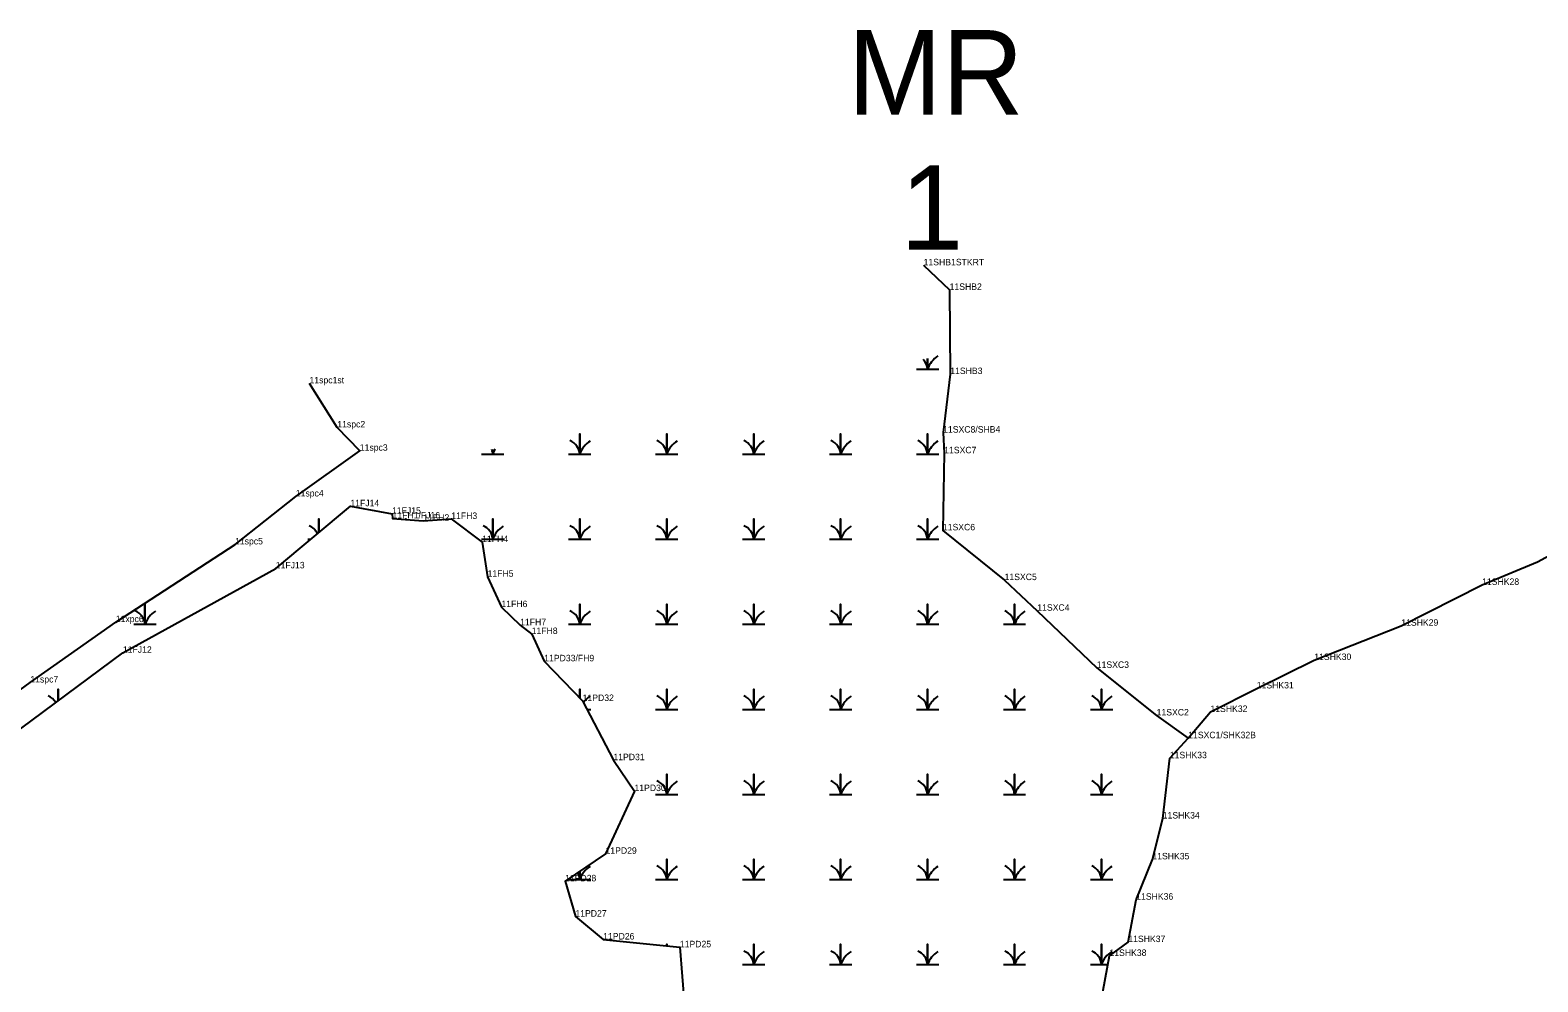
# Model space of a CAD drawing. Extents: x 2072529 to 2268796, y 436423 to 470406.
# Drawn here: x 2231902 to 2233068, y 447664 to 448400 of the extents above; entities that cross this region are included whole.
import ezdxf

# ---------------------------------------------------------------- set-up
doc = ezdxf.new("R2010")
doc.units = 0
for name, color, linetype in [('Default', 7, 'Continuous'), ('Exist Environmental Wetland Boundary', 7, 'Continuous'), ('Exist Environmental Wetland Boundary Cogo Comment', 7, 'Continuous'), ('Exist Hydro Jurisdictional Stream or Body of Water NEU Mitigable', 7, 'Continuous'), ('Exist Hydro Jurisdictional Stream or Body of Water NEU Mitigable Cogo Comment', 7, 'Continuous'), ('Exist Hydro Swamp or Marsh', 7, 'Continuous'), ('Old_Level_20', 7, 'Continuous')]:
    doc.layers.add(name, color=color, linetype=linetype)

msp = doc.modelspace()

# ---------------------------------------------------------------- linework, layer by layer
at = {"layer": 'Exist Environmental Wetland Boundary'}
msp.add_lwpolyline([(2231807.6, 447794.9), (2231974.2, 447918.4), (2232092.4, 447983.7), (2232150.1, 448031.7), (2232182.3, 448025.9), (2232182.7, 448022.3), (2232206.5, 448020.5), (2232228.1, 448021.9), (2232252, 448004), (2232256.2, 447977.2), (2232266.9, 447953.7), (2232281.4, 447939.7), (2232290.3, 447932.9), (2232300, 447911.8), (2232329.7, 447881.1), (2232353.5, 447835.3), (2232369.8, 447811.4), (2232347.4, 447762.9), (2232316.1, 447741.6), (2232324.1, 447714.3), (2232345.6, 447696.6), (2232404.9, 447690.6), (2232408.4, 447645.4)], dxfattribs=at)
at = {"layer": 'Exist Hydro Jurisdictional Stream or Body of Water NEU Mitigable'}
for points in [[(2232593.4, 448218.1), (2232613.5, 448199.1), (2232614, 448134), (2232608.5, 448088.7)], [(2230769.4, 447951.9), (2230820.5, 447870.1), (2230875.8, 447771.9), (2230917.6, 447710.6), (2230955.8, 447692.5), (2231037.5, 447706.9), (2231173.4, 447735.5), (2231315.3, 447761.1), (2231455.2, 447786.8), (2231613.2, 447790.3), (2231730.8, 447794.1), (2231802.3, 447822), (2231902.6, 447895.4), (2231968.7, 447942.1), (2232060.9, 448002.2), (2232107.9, 448039.3), (2232157.4, 448074.7), (2232140, 448092.7), (2232118.5, 448126.8)], [(2232608.5, 448088.7), (2232609.3, 448072.7), (2232608.3, 448013.1), (2232656, 447974.6), (2232681.3, 447950.9), (2232727.3, 447906.7), (2232773.6, 447869.9), (2232798, 447852.3)], [(2232612.7, 447313.1), (2232637.1, 447372.3), (2232659.7, 447420.7), (2232659.3, 447443.5), (2232665.8, 447482.5), (2232689.5, 447512.3), (2232693.2, 447533.5), (2232707, 447570), (2232725.1, 447618.2), (2232737.1, 447683.9), (2232751.7, 447694.6), (2232757.8, 447727.4), (2232770.3, 447758.6), (2232778.3, 447790.2), (2232783.8, 447836.8), (2232798, 447852.3), (2232815.2, 447872.6), (2232851, 447890.8), (2232895.5, 447912.8), (2232962.8, 447939.3), (2233025.3, 447970.9), (2233068.1, 447988.8), (2233109.1, 448010.9)]]:
    msp.add_lwpolyline(points, dxfattribs=at)
at = {"layer": 'Exist Hydro Swamp or Marsh'}
for points in [[(2232587.9, 448137.8), (2232596.5, 448137.8), (2232596.5, 448146.1)], [(2232596.5, 448146.1), (2232596.5, 448137.8), (2232605.1, 448137.8)], [(2232318.9, 448072), (2232327.5, 448072), (2232327.5, 448087.7), (2232327.5, 448072), (2232336.1, 448072)], [(2232386.1, 448072), (2232394.7, 448072), (2232394.7, 448087.7), (2232394.7, 448072), (2232403.3, 448072)], [(2232453.4, 448072), (2232462, 448072), (2232462, 448087.7), (2232462, 448072), (2232470.6, 448072)], [(2232520.6, 448072), (2232529.2, 448072), (2232529.2, 448087.7), (2232529.2, 448072), (2232537.8, 448072)], [(2232587.9, 448072), (2232596.5, 448072), (2232596.5, 448087.7), (2232596.5, 448072), (2232605.1, 448072)], [(2232251.6, 448072), (2232260.2, 448072), (2232260.2, 448075.7)], [(2232260.2, 448075.7), (2232260.2, 448072), (2232268.8, 448072)], [(2232125.7, 448011.4), (2232125.7, 448021.9), (2232125.7, 448011.4)], [(2232193, 448021.5), (2232193, 448021.9), (2232193, 448021.5)], [(2232251.6, 448006.2), (2232260.2, 448006.2), (2232260.2, 448021.9), (2232260.2, 448006.2), (2232268.8, 448006.2)], [(2232318.9, 448006.2), (2232327.5, 448006.2), (2232327.5, 448021.9), (2232327.5, 448006.2), (2232336.1, 448006.2)], [(2232386.1, 448006.2), (2232394.7, 448006.2), (2232394.7, 448021.9), (2232394.7, 448006.2), (2232403.3, 448006.2)], [(2232453.4, 448006.2), (2232462, 448006.2), (2232462, 448021.9), (2232462, 448006.2), (2232470.6, 448006.2)], [(2232520.6, 448006.2), (2232529.2, 448006.2), (2232529.2, 448021.9), (2232529.2, 448006.2), (2232537.8, 448006.2)], [(2232587.9, 448006.2), (2232596.5, 448006.2), (2232596.5, 448021.9), (2232596.5, 448006.2), (2232605.1, 448006.2)], [(2232066, 448006.2), (2232067.1, 448006.2)], [(2232117.1, 448006.2), (2232119.4, 448006.2)], [(2231982.6, 447940.4), (2231991.2, 447940.4), (2231991.2, 447956.1), (2231991.2, 447940.4), (2231999.8, 447940.4)], [(2232318.9, 447940.4), (2232327.5, 447940.4), (2232327.5, 447956.1), (2232327.5, 447940.4), (2232336.1, 447940.4)], [(2232386.1, 447940.4), (2232394.7, 447940.4), (2232394.7, 447956.1), (2232394.7, 447940.4), (2232403.3, 447940.4)], [(2232453.4, 447940.4), (2232462, 447940.4), (2232462, 447956.1), (2232462, 447940.4), (2232470.6, 447940.4)], [(2232520.6, 447940.4), (2232529.2, 447940.4), (2232529.2, 447956.1), (2232529.2, 447940.4), (2232537.8, 447940.4)], [(2232587.9, 447940.4), (2232596.5, 447940.4), (2232596.5, 447956.1), (2232596.5, 447940.4), (2232605.1, 447940.4)], [(2232655.1, 447940.4), (2232663.7, 447940.4), (2232663.7, 447956.1), (2232663.7, 447940.4), (2232672.3, 447940.4)], [(2231924, 447881.2), (2231924, 447890.3), (2231924, 447881.2)], [(2232327.5, 447883.4), (2232327.5, 447890.3), (2232327.5, 447883.4)], [(2232386.1, 447874.6), (2232394.7, 447874.6), (2232394.7, 447890.3), (2232394.7, 447874.6), (2232403.3, 447874.6)], [(2232453.4, 447874.6), (2232462, 447874.6), (2232462, 447890.3), (2232462, 447874.6), (2232470.6, 447874.6)], [(2232520.6, 447874.6), (2232529.2, 447874.6), (2232529.2, 447890.3), (2232529.2, 447874.6), (2232537.8, 447874.6)], [(2232587.9, 447874.6), (2232596.5, 447874.6), (2232596.5, 447890.3), (2232596.5, 447874.6), (2232605.1, 447874.6)], [(2232655.1, 447874.6), (2232663.7, 447874.6), (2232663.7, 447890.3), (2232663.7, 447874.6), (2232672.3, 447874.6)], [(2232722.4, 447874.6), (2232731, 447874.6), (2232731, 447890.3), (2232731, 447874.6), (2232739.6, 447874.6)], [(2232333.1, 447874.6), (2232336.1, 447874.6)], [(2232386.1, 447808.8), (2232394.7, 447808.8), (2232394.7, 447824.5), (2232394.7, 447808.8), (2232403.3, 447808.8)], [(2232453.4, 447808.8), (2232462, 447808.8), (2232462, 447824.5), (2232462, 447808.8), (2232470.6, 447808.8)], [(2232520.6, 447808.8), (2232529.2, 447808.8), (2232529.2, 447824.5), (2232529.2, 447808.8), (2232537.8, 447808.8)], [(2232587.9, 447808.8), (2232596.5, 447808.8), (2232596.5, 447824.5), (2232596.5, 447808.8), (2232605.1, 447808.8)], [(2232655.1, 447808.8), (2232663.7, 447808.8), (2232663.7, 447824.5), (2232663.7, 447808.8), (2232672.3, 447808.8)], [(2232722.4, 447808.8), (2232731, 447808.8), (2232731, 447824.5), (2232731, 447808.8), (2232739.6, 447808.8)], [(2232386.1, 447743), (2232394.7, 447743), (2232394.7, 447758.7), (2232394.7, 447743), (2232403.3, 447743)], [(2232453.4, 447743), (2232462, 447743), (2232462, 447758.7), (2232462, 447743), (2232470.6, 447743)], [(2232520.6, 447743), (2232529.2, 447743), (2232529.2, 447758.7), (2232529.2, 447743), (2232537.8, 447743)], [(2232587.9, 447743), (2232596.5, 447743), (2232596.5, 447758.7), (2232596.5, 447743), (2232605.1, 447743)], [(2232655.1, 447743), (2232663.7, 447743), (2232663.7, 447758.7), (2232663.7, 447743), (2232672.3, 447743)], [(2232722.4, 447743), (2232731, 447743), (2232731, 447758.7), (2232731, 447743), (2232739.6, 447743)], [(2232318.9, 447743), (2232327.5, 447743), (2232327.5, 447749.4)], [(2232327.5, 447749.4), (2232327.5, 447743), (2232336.1, 447743)], [(2232394.7, 447691.7), (2232394.7, 447692.9), (2232394.7, 447691.7)], [(2232453.4, 447677.2), (2232462, 447677.2), (2232462, 447692.9), (2232462, 447677.2), (2232470.6, 447677.2)], [(2232520.6, 447677.2), (2232529.2, 447677.2), (2232529.2, 447692.9), (2232529.2, 447677.2), (2232537.8, 447677.2)], [(2232587.9, 447677.2), (2232596.5, 447677.2), (2232596.5, 447692.9), (2232596.5, 447677.2), (2232605.1, 447677.2)], [(2232655.1, 447677.2), (2232663.7, 447677.2), (2232663.7, 447692.9), (2232663.7, 447677.2), (2232672.3, 447677.2)], [(2232722.4, 447677.2), (2232731, 447677.2), (2232731, 447692.9), (2232731, 447677.2), (2232735.8, 447677.2)]]:
    msp.add_lwpolyline(points, dxfattribs=at)
for centre, radius, start, end in [((2232614.7, 448131.7), 19.2, 122.1274, 161.6222), ((2232584.2, 448136.9), 12.3, 4.1403, 43.3796), ((2232315.2, 448071.1), 12.3, 4.1403, 67.535), ((2232345.7, 448065.9), 19.2, 122.1274, 161.6222), ((2232382.5, 448071.1), 12.3, 4.1403, 67.535), ((2232413, 448065.9), 19.2, 122.1274, 161.6222), ((2232449.7, 448071.1), 12.3, 4.1403, 67.535), ((2232480.2, 448065.9), 19.2, 122.1274, 161.6222), ((2232517, 448071.1), 12.3, 4.1403, 67.535), ((2232547.5, 448065.9), 19.2, 122.1274, 161.6222), ((2232584.2, 448071.1), 12.3, 4.1403, 67.535), ((2232614.7, 448065.9), 19.2, 122.1274, 161.6222), ((2232248, 448071.1), 12.3, 4.1403, 21.2935), ((2232278.5, 448065.9), 19.2, 148.249, 161.6222), ((2232113.5, 448005.3), 12.3, 25.1043, 67.535), ((2232248, 448005.3), 12.3, 4.1403, 67.535), ((2232278.5, 448000.1), 19.2, 122.1274, 161.6222), ((2232315.2, 448005.3), 12.3, 4.1403, 67.535), ((2232345.7, 448000.1), 19.2, 122.1274, 161.6222), ((2232382.5, 448005.3), 12.3, 4.1403, 67.535), ((2232413, 448000.1), 19.2, 122.1274, 161.6222), ((2232449.7, 448005.3), 12.3, 4.1403, 67.535), ((2232480.2, 448000.1), 19.2, 122.1274, 161.6222), ((2232517, 448005.3), 12.3, 4.1403, 67.535), ((2232547.5, 448000.1), 19.2, 122.1274, 161.6222), ((2232584.2, 448005.3), 12.3, 4.1403, 67.535), ((2232614.7, 448000.1), 19.2, 122.1274, 161.6222), ((2231979, 447939.5), 12.3, 4.1403, 67.535), ((2232009.5, 447934.3), 19.2, 122.1274, 161.6222), ((2232315.2, 447939.5), 12.3, 4.1403, 67.535), ((2232345.7, 447934.3), 19.2, 122.1274, 161.6222), ((2232382.5, 447939.5), 12.3, 4.1403, 67.535), ((2232413, 447934.3), 19.2, 122.1274, 161.6222), ((2232449.7, 447939.5), 12.3, 4.1403, 67.535), ((2232480.2, 447934.3), 19.2, 122.1274, 161.6222), ((2232517, 447939.5), 12.3, 4.1403, 67.535), ((2232547.5, 447934.3), 19.2, 122.1274, 161.6222), ((2232584.2, 447939.5), 12.3, 4.1403, 67.535), ((2232614.7, 447934.3), 19.2, 122.1274, 161.6222), ((2232651.5, 447939.5), 12.3, 4.1403, 67.535), ((2232682, 447934.3), 19.2, 122.1274, 161.6222), ((2231911.7, 447873.7), 12.3, 30.5555, 67.535), ((2232345.7, 447868.5), 19.2, 122.1274, 143.4024), ((2232382.5, 447873.7), 12.3, 4.1403, 67.535), ((2232413, 447868.5), 19.2, 122.1274, 161.6222), ((2232449.7, 447873.7), 12.3, 4.1403, 67.535), ((2232480.2, 447868.5), 19.2, 122.1274, 161.6222), ((2232517, 447873.7), 12.3, 4.1403, 67.535), ((2232547.5, 447868.5), 19.2, 122.1274, 161.6222), ((2232584.2, 447873.7), 12.3, 4.1403, 67.535), ((2232614.7, 447868.5), 19.2, 122.1274, 161.6222), ((2232651.5, 447873.7), 12.3, 4.1403, 67.535), ((2232682, 447868.5), 19.2, 122.1274, 161.6222), ((2232718.7, 447873.7), 12.3, 4.1403, 67.535), ((2232749.2, 447868.5), 19.2, 122.1274, 161.6222), ((2232382.5, 447807.9), 12.3, 4.1403, 67.535), ((2232413, 447802.7), 19.2, 122.1274, 161.6222), ((2232449.7, 447807.9), 12.3, 4.1403, 67.535), ((2232480.2, 447802.7), 19.2, 122.1274, 161.6222), ((2232517, 447807.9), 12.3, 4.1403, 67.535), ((2232547.5, 447802.7), 19.2, 122.1274, 161.6222), ((2232584.2, 447807.9), 12.3, 4.1403, 67.535), ((2232614.7, 447802.7), 19.2, 122.1274, 161.6222), ((2232651.5, 447807.9), 12.3, 4.1403, 67.535), ((2232682, 447802.7), 19.2, 122.1274, 161.6222), ((2232718.7, 447807.9), 12.3, 4.1403, 67.535), ((2232749.2, 447802.7), 19.2, 122.1274, 161.6222), ((2232345.7, 447736.9), 19.2, 122.1274, 161.6222), ((2232382.5, 447742.1), 12.3, 4.1403, 67.535), ((2232413, 447736.9), 19.2, 122.1274, 161.6222), ((2232449.7, 447742.1), 12.3, 4.1403, 67.535), ((2232480.2, 447736.9), 19.2, 122.1274, 161.6222), ((2232517, 447742.1), 12.3, 4.1403, 67.535), ((2232547.5, 447736.9), 19.2, 122.1274, 161.6222), ((2232584.2, 447742.1), 12.3, 4.1403, 67.535), ((2232614.7, 447736.9), 19.2, 122.1274, 161.6222), ((2232651.5, 447742.1), 12.3, 4.1403, 67.535), ((2232682, 447736.9), 19.2, 122.1274, 161.6222), ((2232718.7, 447742.1), 12.3, 4.1403, 67.535), ((2232749.2, 447736.9), 19.2, 122.1274, 161.6222), ((2232315.2, 447742.1), 12.3, 4.1403, 30.1347), ((2232449.7, 447676.3), 12.3, 4.1403, 67.535), ((2232480.2, 447671.1), 19.2, 122.1274, 161.6222), ((2232517, 447676.3), 12.3, 4.1403, 67.535), ((2232547.5, 447671.1), 19.2, 122.1274, 161.6222), ((2232584.2, 447676.3), 12.3, 4.1403, 67.535), ((2232614.7, 447671.1), 19.2, 122.1274, 161.6222), ((2232651.5, 447676.3), 12.3, 4.1403, 67.535), ((2232682, 447671.1), 19.2, 122.1274, 161.6222), ((2232718.7, 447676.3), 12.3, 4.1403, 67.535), ((2232749.2, 447671.1), 19.2, 122.1274, 161.6222)]:
    msp.add_arc(centre, radius, start, end, dxfattribs=at)
at = {"layer": 'Old_Level_20'}
for p, q in [((2232593.4, 448218.1), (2232593.4, 448218.1)), ((2232613.5, 448199.1), (2232613.5, 448199.1)), ((2232118.5, 448126.8), (2232118.5, 448126.8)), ((2232614, 448134), (2232614, 448134)), ((2232140, 448092.7), (2232140, 448092.7)), ((2232608.5, 448088.7), (2232608.5, 448088.7)), ((2232157.4, 448074.7), (2232157.4, 448074.7)), ((2232609.3, 448072.7), (2232609.3, 448072.7)), ((2232107.9, 448039.3), (2232107.9, 448039.3)), ((2232150.1, 448031.7), (2232150.1, 448031.7)), ((2232182.3, 448025.9), (2232182.3, 448025.9)), ((2232182.7, 448022.3), (2232182.7, 448022.3)), ((2232206.5, 448020.5), (2232206.5, 448020.5)), ((2232228.1, 448021.9), (2232228.1, 448021.9)), ((2232608.3, 448013.1), (2232608.3, 448013.1)), ((2232060.9, 448002.2), (2232060.9, 448002.2)), ((2232252, 448004), (2232252, 448004)), ((2232092.4, 447983.7), (2232092.4, 447983.7)), ((2233068.1, 447988.8), (2233068.1, 447988.8)), ((2232256.2, 447977.2), (2232256.2, 447977.2)), ((2232656, 447974.6), (2232656, 447974.6)), ((2233025.3, 447970.9), (2233025.3, 447970.9)), ((2232266.9, 447953.7), (2232266.9, 447953.7)), ((2232681.3, 447950.9), (2232681.3, 447950.9)), ((2231968.7, 447942.1), (2231968.7, 447942.1)), ((2232281.4, 447939.7), (2232281.4, 447939.7)), ((2232962.8, 447939.3), (2232962.8, 447939.3)), ((2232290.3, 447932.9), (2232290.3, 447932.9)), ((2231974.2, 447918.4), (2231974.2, 447918.4)), ((2232300, 447911.8), (2232300, 447911.8)), ((2232727.3, 447906.7), (2232727.3, 447906.7)), ((2232895.5, 447912.8), (2232895.5, 447912.8)), ((2231902.6, 447895.4), (2231902.6, 447895.4)), ((2232851, 447890.8), (2232851, 447890.8)), ((2232329.7, 447881.1), (2232329.7, 447881.1)), ((2232773.6, 447869.9), (2232773.6, 447869.9)), ((2232815.2, 447872.6), (2232815.2, 447872.6)), ((2232798, 447852.3), (2232798, 447852.3)), ((2232353.5, 447835.3), (2232353.5, 447835.3)), ((2232783.8, 447836.8), (2232783.8, 447836.8)), ((2232369.8, 447811.4), (2232369.8, 447811.4)), ((2232778.3, 447790.2), (2232778.3, 447790.2)), ((2232347.4, 447762.9), (2232347.4, 447762.9)), ((2232770.3, 447758.6), (2232770.3, 447758.6)), ((2232316.1, 447741.6), (2232316.1, 447741.6)), ((2232757.8, 447727.4), (2232757.8, 447727.4)), ((2232324.1, 447714.3), (2232324.1, 447714.3)), ((2232345.6, 447696.6), (2232345.6, 447696.6)), ((2232751.7, 447694.6), (2232751.7, 447694.6)), ((2232404.9, 447690.6), (2232404.9, 447690.6)), ((2232737.1, 447683.9), (2232737.1, 447683.9))]:
    msp.add_line(p, q, dxfattribs=at)

# ---------------------------------------------------------------- texts
at = {"layer": 'Default'}
for s, height, p in [('MR', 65.34, (2232534.8, 448334.7)), ('1', 65.3, (2232575.5, 448230.1))]:
    msp.add_text(s, height=height, dxfattribs=at).set_placement(p)
at = {"layer": 'Exist Environmental Wetland Boundary Cogo Comment'}
for s, p in [('11FJ14', (2232150.1, 448031.7)), ('11FJ15', (2232182.3, 448025.9)), ('11FH1/FJ16', (2232182.7, 448022.3)), ('11FH2', (2232206.5, 448020.5)), ('11FH3', (2232228.1, 448021.9)), ('11FH4', (2232252, 448004)), ('11FJ13', (2232092.4, 447983.7)), ('11FH5', (2232256.2, 447977.2)), ('11FH6', (2232266.9, 447953.7)), ('11FH7', (2232281.4, 447939.7)), ('11FH8', (2232290.3, 447932.9)), ('11FJ12', (2231974.2, 447918.4)), ('11PD33/FH9', (2232300, 447911.8)), ('11PD32', (2232329.7, 447881.1)), ('11PD31', (2232353.5, 447835.3)), ('11PD30', (2232369.8, 447811.4)), ('11PD29', (2232347.4, 447762.9)), ('11PD28', (2232316.1, 447741.6)), ('11PD27', (2232324.1, 447714.3)), ('11PD26', (2232345.6, 447696.6)), ('11PD25', (2232404.9, 447690.6))]:
    msp.add_text(s, height=5, dxfattribs=at).set_placement(p)
at = {"layer": 'Exist Hydro Jurisdictional Stream or Body of Water NEU Mitigable Cogo Comment'}
for s, p in [('11SHB1STKRT', (2232593.4, 448218.1)), ('11SHB2', (2232613.5, 448199.1)), ('11SHB3', (2232614, 448134)), ('11spc1st', (2232118.5, 448126.8)), ('11spc2', (2232140, 448092.7)), ('11SXC8/SHB4', (2232608.5, 448088.7)), ('11spc3', (2232157.4, 448074.7)), ('11SXC7', (2232609.3, 448072.7)), ('11spc4', (2232107.9, 448039.3)), ('11SXC6', (2232608.3, 448013.1)), ('11spc5', (2232060.9, 448002.2)), ('11SXC5', (2232656, 447974.6)), ('11SHK28', (2233025.3, 447970.9)), ('11SXC4', (2232681.3, 447950.9)), ('11xpc6', (2231968.7, 447942.1)), ('11SHK29', (2232962.8, 447939.3)), ('11SHK30', (2232895.5, 447912.8)), ('11SXC3', (2232727.3, 447906.7)), ('11spc7', (2231902.6, 447895.4)), ('11SHK31', (2232851, 447890.8)), ('11SXC2', (2232773.6, 447869.9)), ('11SHK32', (2232815.2, 447872.6)), ('11SXC1/SHK32B', (2232798, 447852.3)), ('11SHK33', (2232783.8, 447836.8)), ('11SHK34', (2232778.3, 447790.2)), ('11SHK35', (2232770.3, 447758.6)), ('11SHK36', (2232757.8, 447727.4)), ('11SHK37', (2232751.7, 447694.6)), ('11SHK38', (2232737.1, 447683.9))]:
    msp.add_text(s, height=5, dxfattribs=at).set_placement(p)

doc.saveas('drawing.dxf')
